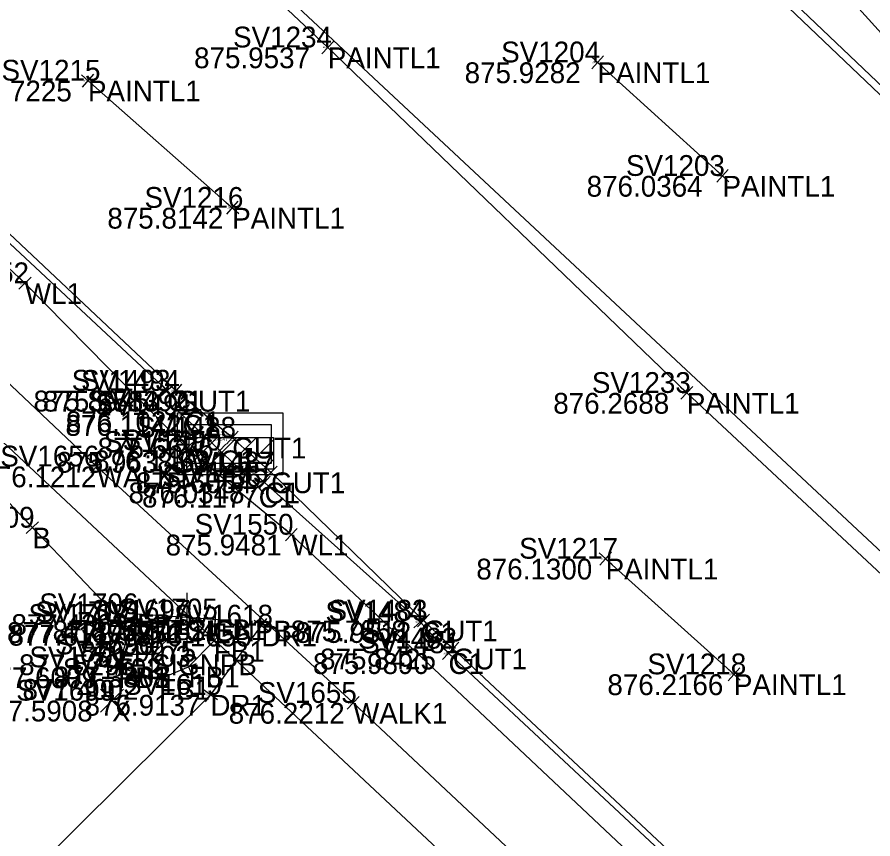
# Model space of a CAD drawing. Extents: x 1469677 to 1493262, y 375219 to 389293.
# Drawn here: x 1480224.64 to 1480274.04, y 379313.52 to 379360.96 of the extents above; entities that cross this region are included whole.
import ezdxf

# ---------------------------------------------------------------- set-up
doc = ezdxf.new("R2010")
doc.units = 0
for name, color, linetype in [('Building', 7, 'Continuous'), ('Default', 7, 'Continuous'), ('DR_X_Drive_Pipe', 7, 'Continuous'), ('DV_X_Lot_Line', 7, 'Continuous'), ('DV_X_Text', 7, 'Continuous'), ('GK_Visualization', 7, 'Continuous'), ('PNTELEV', 7, 'Continuous'), ('RD_P_Text', 7, 'Continuous'), ('RW_P_Esmt_SW', 7, 'Continuous'), ('RW_P_Esmt_U', 7, 'Continuous'), ('RW_X_CL_20', 7, 'Continuous'), ('rw_x_right_of_way', 7, 'Continuous'), ('SV_X_Mon_Cells_Found', 7, 'Continuous'), ('SV_X_Random_Point', 7, 'Continuous'), ('SV_X_Text_Elevation', 7, 'Continuous'), ('text', 7, 'Continuous'), ('Text Border', 7, 'Continuous'), ('Text Property', 7, 'Continuous')]:
    doc.layers.add(name, color=color, linetype=linetype)

msp = doc.modelspace()

# ---------------------------------------------------------------- linework, layer by layer
at = {"layer": 'Building'}
for points in [[(1480349.171, 379259.048), (1480326.954, 379280.06), (1480305.568, 379299.916), (1480284.393, 379319.578), (1480263.301, 379339.268), (1480242.575, 379359.213), (1480224.612, 379376.165), (1480208.191, 379391.527)], [(1480265.361, 379351.797), (1480258.147, 379358.351)], [(1480228.73, 379357.297), (1480237.057, 379349.954)], [(1480258.612, 379329.697), (1480266.018, 379323.022)]]:
    msp.add_lwpolyline(points, dxfattribs=at)
at = {"layer": 'Default'}
msp.add_lwpolyline([(1480232.416, 379324.173), (1480234.446, 379326.119)], dxfattribs=at)
at = {"layer": 'DR_X_Drive_Pipe'}
for points in [[(1480172.622, 379452.503), (1480197.813, 379429.111), (1480212.628, 379415.684), (1480231.592, 379398.237), (1480249.493, 379381.828), (1480253.44, 379378.963), (1480259.284, 379374.539), (1480264.171, 379372.865), (1480269.434, 379369.248), (1480270.598, 379368.157), (1480270.755, 379365.904), (1480271.186, 379363.733), (1480285.468, 379347.959), (1480298.848, 379335.614), (1480313.013, 379322.705), (1480330.745, 379305.601), (1480344.344, 379292.312), (1480351.783, 379285.136)], [(1480327.263, 379249.797), (1480312.798, 379263.799), (1480291.915, 379283.182), (1480274.385, 379298.987), (1480265.401, 379307.725), (1480264.495, 379308.458), (1480240.472, 379331.084), (1480234.677, 379335.863), (1480225.088, 379345.601), (1480208.322, 379361.342), (1480207.346, 379362.25), (1480199.528, 379369.768), (1480193.21, 379375.651), (1480182.823, 379385.139), (1480177.927, 379389.525), (1480169.423, 379398.321), (1480161.035, 379406.189), (1480144.924, 379421.019), (1480134.739, 379430.559), (1480121.485, 379441.998)]]:
    msp.add_lwpolyline(points, dxfattribs=at)
at = {"layer": 'DV_X_Lot_Line'}
msp.add_lwpolyline([(1480327.959, 379242.083), (1480313.163, 379256.356), (1480297.576, 379270.674), (1480283.951, 379284.205), (1480267.344, 379299.69), (1480258.509, 379307.782), (1480244.036, 379321.372), (1480229.243, 379335.021), (1480213.414, 379349.982), (1480196.806, 379366.202), (1480192.296, 379370.271), (1480186.385, 379375.802), (1480181.8, 379379.27), (1480179.258, 379381.212), (1480177.445, 379382.131), (1480174.921, 379382.868), (1480171.98, 379383.537), (1480169.491, 379383.403), (1480167.014, 379382.902), (1480162.891, 379380.83), (1480161.298, 379379.691), (1480158.915, 379377.808)], dxfattribs=at)
at = {"layer": 'PNTELEV'}
for p, q in [((1480242.935, 379358.866), (1480242.215, 379359.56)), ((1480242.228, 379358.853), (1480242.922, 379359.573)), ((1480242.575, 379359.213), (1480242.575, 379359.213)), ((1480258.517, 379358.014), (1480257.777, 379358.687)), ((1480257.811, 379357.98), (1480258.483, 379358.721)), ((1480258.147, 379358.351), (1480258.147, 379358.351)), ((1480228.355, 379357.628), (1480229.105, 379356.966)), ((1480229.06, 379357.672), (1480228.399, 379356.922)), ((1480228.73, 379357.297), (1480228.73, 379357.297)), ((1480265.025, 379351.427), (1480265.697, 379352.168)), ((1480265.731, 379351.461), (1480264.991, 379352.134)), ((1480265.361, 379351.797), (1480265.361, 379351.797)), ((1480236.681, 379350.285), (1480237.432, 379349.623)), ((1480237.387, 379350.329), (1480236.726, 379349.579)), ((1480237.057, 379349.954), (1480237.057, 379349.954)), ((1480224.732, 379345.251), (1480225.444, 379345.952)), ((1480225.439, 379345.245), (1480224.737, 379345.958)), ((1480225.088, 379345.601), (1480225.088, 379345.601)), ((1480232.919, 379339.073), (1480233.676, 379339.727)), ((1480233.624, 379339.022), (1480232.97, 379339.779)), ((1480233.297, 379339.4), (1480233.297, 379339.4)), ((1480234.213, 379339.069), (1480233.447, 379339.711)), ((1480233.509, 379339.006), (1480234.151, 379339.773)), ((1480233.83, 379339.39), (1480233.83, 379339.39)), ((1480263.666, 379338.927), (1480262.935, 379339.609)), ((1480262.959, 379338.903), (1480263.642, 379339.634)), ((1480263.301, 379339.268), (1480263.301, 379339.268)), ((1480234.55, 379337.645), (1480233.824, 379338.332)), ((1480233.843, 379337.626), (1480234.531, 379338.351)), ((1480233.907, 379338.477), (1480234.748, 379337.937)), ((1480234.058, 379337.787), (1480234.598, 379338.628)), ((1480234.187, 379337.989), (1480234.187, 379337.989)), ((1480234.328, 379338.207), (1480234.328, 379338.207)), ((1480237.437, 379336.35), (1480236.692, 379337.017)), ((1480236.731, 379336.311), (1480237.398, 379337.056)), ((1480237.065, 379336.683), (1480237.065, 379336.683)), ((1480235.063, 379335.545), (1480234.291, 379336.181)), ((1480234.359, 379335.477), (1480234.995, 379336.249)), ((1480234.677, 379335.863), (1480234.677, 379335.863)), ((1480236.706, 379335.606), (1480235.975, 379336.288)), ((1480235.999, 379335.582), (1480236.682, 379336.313)), ((1480236.341, 379335.947), (1480236.341, 379335.947)), ((1480229.61, 379334.682), (1480228.876, 379335.36)), ((1480228.904, 379334.654), (1480229.582, 379335.389)), ((1480229.243, 379335.021), (1480229.243, 379335.021)), ((1480239.66, 379334.332), (1480238.943, 379335.028)), ((1480238.953, 379334.321), (1480239.65, 379335.039)), ((1480239.297, 379333.763), (1480238.552, 379334.43)), ((1480238.591, 379333.724), (1480239.258, 379334.469)), ((1480239.302, 379334.68), (1480239.302, 379334.68)), ((1480238.992, 379334.145), (1480238.18, 379333.56)), ((1480238.878, 379333.447), (1480238.294, 379334.258)), ((1480238.925, 379334.096), (1480238.925, 379334.096)), ((1480238.586, 379333.852), (1480238.586, 379333.852)), ((1480225.16, 379331.144), (1480225.884, 379331.834)), ((1480225.867, 379331.128), (1480225.177, 379331.851)), ((1480225.522, 379331.489), (1480225.522, 379331.489)), ((1480240.835, 379330.741), (1480240.108, 379331.427)), ((1480240.129, 379330.72), (1480240.814, 379331.448)), ((1480240.472, 379331.084), (1480240.472, 379331.084)), ((1480258.24, 379330.032), (1480258.983, 379329.363)), ((1480258.946, 379330.069), (1480258.277, 379329.326)), ((1480258.612, 379329.697), (1480258.612, 379329.697)), ((1480231.538, 379325.994), (1480231.604, 379326.992)), ((1480232.07, 379326.46), (1480231.072, 379326.526)), ((1480231.571, 379326.493), (1480231.571, 379326.493)), ((1480236.051, 379325.696), (1480236.121, 379326.694)), ((1480248.47, 379325.78), (1480247.748, 379326.472)), ((1480247.763, 379325.765), (1480248.455, 379326.487)), ((1480230.52, 379325.533), (1480231.244, 379326.224)), ((1480231.227, 379325.517), (1480230.537, 379326.24)), ((1480231.683, 379325.757), (1480230.849, 379326.311)), ((1480231.543, 379326.451), (1480230.989, 379325.617)), ((1480231.266, 379326.034), (1480231.266, 379326.034)), ((1480235.587, 379326.23), (1480236.585, 379326.16)), ((1480236.086, 379326.195), (1480236.086, 379326.195)), ((1480239.139, 379325.541), (1480238.333, 379326.133)), ((1480239.032, 379326.24), (1480238.44, 379325.434)), ((1480247.548, 379325.701), (1480248.289, 379326.371)), ((1480248.254, 379325.665), (1480247.583, 379326.407)), ((1480247.919, 379326.036), (1480247.919, 379326.036)), ((1480248.109, 379326.126), (1480248.109, 379326.126)), ((1480230.882, 379325.878), (1480230.882, 379325.878)), ((1480238.736, 379325.837), (1480238.736, 379325.837)), ((1480235.641, 379325.295), (1480236.355, 379324.594)), ((1480235.647, 379324.588), (1480236.349, 379325.301)), ((1480235.998, 379324.944), (1480235.998, 379324.944)), ((1480249.909, 379323.899), (1480249.177, 379324.581)), ((1480249.202, 379323.874), (1480249.884, 379324.605)), ((1480250.164, 379324.164), (1480249.435, 379324.848)), ((1480249.458, 379324.141), (1480250.141, 379324.871)), ((1480249.8, 379324.506), (1480249.8, 379324.506)), ((1480249.543, 379324.24), (1480249.543, 379324.24)), ((1480229.989, 379323.563), (1480230.951, 379323.289)), ((1480230.607, 379323.907), (1480230.333, 379322.945)), ((1480234.08, 379323.269), (1480235.002, 379323.656)), ((1480234.348, 379323.924), (1480234.734, 379323.001)), ((1480230.47, 379323.426), (1480230.47, 379323.426)), ((1480232.979, 379323.231), (1480232.705, 379322.269)), ((1480234.541, 379323.463), (1480234.541, 379323.463)), ((1480265.646, 379323.357), (1480266.389, 379322.688)), ((1480266.352, 379323.394), (1480265.683, 379322.651)), ((1480266.018, 379323.022), (1480266.018, 379323.022)), ((1480232.361, 379322.887), (1480233.323, 379322.613)), ((1480232.842, 379322.75), (1480232.842, 379322.75)), ((1480236.203, 379321.541), (1480235.397, 379322.133)), ((1480236.096, 379322.24), (1480235.504, 379321.434)), ((1480235.8, 379321.837), (1480235.8, 379321.837)), ((1480244.401, 379321.029), (1480243.671, 379321.714)), ((1480243.694, 379321.007), (1480244.378, 379321.736)), ((1480244.036, 379321.372), (1480244.036, 379321.372))]:
    msp.add_line(p, q, dxfattribs=at)
at = {"layer": 'RD_P_Text'}
for points in [[(1480186.975, 379439.363), (1480207.407, 379420.301), (1480210.41, 379417.305), (1480211.712, 379416.16), (1480212.774, 379415.29), (1480213.67, 379414.243), (1480215.361, 379412.945), (1480216.632, 379411.517), (1480217.745, 379410.456), (1480218.76, 379409.536), (1480221.908, 379406.565), (1480233.156, 379396.15), (1480249.934, 379380.311), (1480262.014, 379368.886), (1480262.346, 379369.254), (1480264.513, 379367.165), (1480266.627, 379365.06), (1480266.41, 379364.736), (1480284.493, 379347.537), (1480298.919, 379333.838), (1480300.736, 379332.585), (1480315.855, 379318.308), (1480323.784, 379310.749)], [(1480186.493, 379438.955), (1480206.919, 379419.855), (1480210.187, 379416.932), (1480211.433, 379415.804), (1480213.11, 379414.171), (1480218.471, 379409.217), (1480217.005, 379410.473), (1480215.222, 379412.175), (1480221.495, 379406.235), (1480232.955, 379395.538), (1480249.633, 379380.044), (1480261.648, 379368.645), (1480263.97, 379366.423), (1480266.337, 379364.241), (1480284.168, 379347.237), (1480298.679, 379333.414), (1480300.396, 379332.229), (1480315.326, 379318.045), (1480323.87, 379309.98), (1480343.087, 379291.663), (1480360.248, 379275.585)], [(1480264.304, 379310.926), (1480249.8, 379324.506), (1480248.109, 379326.126), (1480239.302, 379334.68), (1480237.065, 379336.683), (1480233.83, 379339.39), (1480215.875, 379356.288), (1480200.731, 379370.664), (1480190.903, 379379.712), (1480187.53, 379382.642), (1480185.615, 379384.173), (1480181.928, 379385.583), (1480179.411, 379386.173), (1480174.793, 379387.235), (1480172.715, 379387.432), (1480170.332, 379387.359), (1480168.876, 379387.382), (1480166.808, 379386.944), (1480164.881, 379386.368), (1480162.883, 379385.531), (1480159.898, 379383.853), (1480158.052, 379382.754), (1480156.183, 379381.403), (1480155.05, 379380.342)], [(1480264.058, 379310.698), (1480249.543, 379324.24), (1480247.919, 379326.036), (1480238.925, 379334.096), (1480238.586, 379333.852), (1480236.341, 379335.947), (1480234.187, 379337.989), (1480234.328, 379338.207), (1480233.297, 379339.4), (1480215.447, 379356.074)]]:
    msp.add_lwpolyline(points, dxfattribs=at)
at = {"layer": 'RW_P_Esmt_U'}
for p, q in [((1480229.449, 379320.836), (1480230.783, 379322.171)), ((1480229.449, 379322.171), (1480230.783, 379320.836))]:
    msp.add_line(p, q, dxfattribs=at)
at = {"layer": 'RW_X_CL_20'}
for p, q in [((1480236.94, 379338.114), (1480236.94, 379338.114)), ((1480236.94, 379337.447), (1480236.94, 379337.447)), ((1480236.94, 379336.697), (1480236.94, 379336.697)), ((1480236.94, 379336.697), (1480236.94, 379336.697)), ((1480234.565, 379336.322), (1480234.565, 379336.322)), ((1480236.94, 379336.322), (1480236.94, 379336.322)), ((1480239.315, 379336.322), (1480239.315, 379336.322)), ((1480236.94, 379335.197), (1480236.94, 379335.197)), ((1480236.94, 379334.531), (1480236.94, 379334.531))]:
    msp.add_line(p, q, dxfattribs=at)
at = {"layer": 'rw_x_right_of_way'}
for p, q in [((1480234.446, 379327.719), (1480234.446, 379324.519)), ((1480234.446, 379326.119), (1480232.846, 379326.119)), ((1480232.416, 379325.773), (1480232.416, 379322.573)), ((1480232.416, 379324.173), (1480230.816, 379324.173))]:
    msp.add_line(p, q, dxfattribs=at)
at = {"layer": 'SV_X_Mon_Cells_Found'}
msp.add_lwpolyline([(1477164.629, 382297.849), (1479615.888, 379904.59), (1480413.414, 379159.216)], dxfattribs=at)
at = {"layer": 'SV_X_Random_Point'}
for p, q in [((1480234.44, 379334.939), (1480236.194, 379336.697)), ((1480234.44, 379336.071), (1480235.064, 379336.697)), ((1480235.496, 379334.864), (1480237.324, 379336.697)), ((1480236.625, 379334.864), (1480238.454, 379336.697)), ((1480237.755, 379334.864), (1480239.44, 379336.553)), ((1480238.885, 379334.864), (1480239.44, 379335.42))]:
    msp.add_line(p, q, dxfattribs=at)
for points in [[(1480233.898, 379338.115), (1480239.982, 379338.115), (1480239.982, 379334.531), (1480233.898, 379334.531)], [(1480234.565, 379337.447), (1480239.315, 379337.447), (1480239.315, 379335.197), (1480234.565, 379335.197)], [(1480234.44, 379336.697), (1480239.44, 379336.697), (1480239.44, 379334.864), (1480234.44, 379334.864)]]:
    msp.add_lwpolyline(points, close=True, dxfattribs=at)
at = {"layer": 'SV_X_Text_Elevation'}
msp.add_line((1479636.611, 379926.284), (1480557.828, 379065.308), dxfattribs=at)
at = {"layer": 'text'}
msp.add_lwpolyline([(1480230.882, 379325.878), (1480225.522, 379331.489), (1480218.264, 379339.152), (1480211.865, 379343.732), (1480205.22, 379349.624), (1480204.187, 379352.051), (1480200.993, 379355.729), (1480195.628, 379356.44), (1480192.91, 379360.091)], dxfattribs=at)
at = {"layer": 'Text Border'}
msp.add_lwpolyline([(1480238.736, 379325.837), (1480235.8, 379321.837), (1480220.406, 379306.568)], dxfattribs=at)
at = {"layer": 'Text Property'}
msp.add_lwpolyline([(1480230.47, 379323.426), (1480232.842, 379322.75), (1480234.541, 379323.463), (1480235.998, 379324.944), (1480236.086, 379326.195), (1480231.571, 379326.493), (1480231.266, 379326.034)], close=True, dxfattribs=at)

# ---------------------------------------------------------------- texts
at = {"layer": 'DV_X_Text'}
for s, height, p in [('875.9537', 1.2, (1480234.856, 379358.013)), ('875.95', 0.06, (1480242.294, 379359.153)), ('875.9282', 1.2, (1480250.475, 379357.151)), ('875.93', 0.06, (1480257.866, 379358.291)), ('875.7225', 1.2, (1480221.105, 379356.097)), ('875.72', 0.06, (1480228.451, 379357.237)), ('876.0364', 1.2, (1480257.519, 379350.597)), ('876.04', 0.06, (1480265.075, 379351.737)), ('875.8142', 1.2, (1480229.848, 379348.754)), ('875.81', 0.06, (1480236.799, 379349.894)), ('875.85', 0.06, (1480224.808, 379345.541)), ('875.8945', 1.2, (1480225.588, 379338.2)), ('875.6583', 1.2, (1480226.13, 379338.19)), ('875.89', 0.06, (1480233.016, 379339.34)), ('875.66', 0.06, (1480233.545, 379339.33)), ('876.2688', 1.2, (1480255.591, 379338.068)), ('876.27', 0.06, (1480263.021, 379339.208)), ('876.1142', 1.2, (1480227.433, 379336.789)), ('876.1021', 1.2, (1480227.457, 379337.007)), ('876.11', 0.06, (1480233.952, 379337.929)), ('876.10', 0.06, (1480234.065, 379338.147)), ('875.6676', 1.2, (1480229.289, 379335.483)), ('875.6547', 0.2, (1480235.655, 379336.497)), ('875.67', 0.06, (1480236.784, 379336.623)), ('875.65', 0.01, (1480236.893, 379336.687)), ('875.9638', 1.2, (1480226.929, 379334.663)), ('876.1463', 1.2, (1480229.085, 379334.747)), ('875.96', 0.06, (1480234.392, 379335.803)), ('876.15', 0.06, (1480236.084, 379335.887)), ('876.1212', 1.2, (1480222.517, 379333.821)), ('876.12', 0.06, (1480228.986, 379334.961)), ('875.6054', 1.2, (1480231.497, 379333.48)), ('875.61', 0.06, (1480239.043, 379334.62)), ('876.0348', 1.2, (1480231.073, 379332.896)), ('876.1177', 1.2, (1480231.85, 379332.652)), ('876.03', 0.06, (1480238.638, 379334.036)), ('876.12', 0.06, (1480238.329, 379333.792)), ('877.39', 0.06, (1480225.241, 379331.429)), ('875.9481', 1.2, (1480233.213, 379329.884)), ('875.95', 0.06, (1480240.191, 379331.024)), ('876.1300', 1.2, (1480251.148, 379328.497)), ('876.13', 0.06, (1480258.355, 379329.637)), ('877.4361', 1.2, (1480224.313, 379325.293)), ('877.44', 0.06, (1480231.292, 379326.433)), ('877.4189', 1.2, (1480224.058, 379324.834)), ('877.0577', 1.2, (1480226.689, 379324.919)), ('876.8182', 1.2, (1480228.868, 379324.995)), ('877.42', 0.06, (1480230.987, 379325.974)), ('877.06', 0.06, (1480234.157, 379326.059)), ('876.82', 0.06, (1480235.805, 379326.135)), ('875.7858', 1.2, (1480240.437, 379324.926)), ('875.9512', 1.2, (1480240.701, 379324.836)), ('875.95', 0.06, (1480247.638, 379325.976)), ('875.79', 0.06, (1480247.829, 379326.066)), ('877.6117', 1.2, (1480224.147, 379324.678)), ('877.61', 0.06, (1480230.624, 379325.818)), ('876.1655', 1.2, (1480231.49, 379324.637)), ('876.17', 0.06, (1480238.479, 379325.777)), ('876.9975', 1.2, (1480228.279, 379323.744)), ('877.00', 0.06, (1480235.708, 379324.884)), ('875.8425', 1.2, (1480242.128, 379323.306)), ('875.84', 0.06, (1480249.52, 379324.446)), ('877.5295', 1.2, (1480224.754, 379322.973)), ('877.53', 0.06, (1480232.137, 379324.113)), ('875.9890', 1.2, (1480241.72, 379323.04)), ('875.99', 0.06, (1480249.261, 379324.18)), ('877.6009', 1.2, (1480222.552, 379322.226)), ('877.3803', 1.2, (1480226.746, 379322.263)), ('877.60', 0.06, (1480230.185, 379323.366)), ('877.38', 0.06, (1480234.26, 379323.403)), ('876.2166', 1.2, (1480258.715, 379321.822)), ('876.22', 0.06, (1480265.738, 379322.962)), ('877.4002', 1.2, (1480224.953, 379321.55)), ('877.40', 0.06, (1480232.557, 379322.69)), ('877.5908', 1.2, (1480222.312, 379320.303)), ('876.9137', 1.2, (1480228.535, 379320.637)), ('876.91', 0.06, (1480235.541, 379321.777)), ('877.59', 0.06, (1480229.836, 379321.443)), ('876.2212', 1.2, (1480236.856, 379320.172)), ('876.22', 0.06, (1480243.756, 379321.312))]:
    msp.add_text(s, height=height, dxfattribs=at).set_placement(p)
at = {"layer": 'GK_Visualization'}
for s, height, p in [('PAINTL1', 1.2, (1480242.575, 379358.013)), ('PAINTL1', 1.2, (1480258.147, 379357.151)), ('PAINTL1', 1.2, (1480228.73, 379356.097)), ('PAINTL1', 1.2, (1480265.361, 379350.597)), ('PAINTL1', 1.2, (1480237.057, 379348.754)), ('WL1', 1.2, (1480225.088, 379344.401)), ('C1', 1.2, (1480233.297, 379338.2)), ('GUT1', 1.2, (1480233.83, 379338.19)), ('PAINTL1', 1.2, (1480263.301, 379338.068)), ('C1', 1.2, (1480234.187, 379336.789)), ('C1', 1.2, (1480234.328, 379337.007)), ('CB-3', 0.2, (1480236.94, 379336.497)), ('GUT1', 1.2, (1480237.065, 379335.483)), ('WL1', 1.2, (1480234.677, 379334.663)), ('C1', 1.2, (1480236.341, 379334.747)), ('WALK1', 1.2, (1480229.243, 379333.821)), ('GUT1', 1.2, (1480239.302, 379333.48)), ('C1', 1.2, (1480238.586, 379332.652)), ('C1', 1.2, (1480238.925, 379332.896)), ('B', 1.2, (1480225.522, 379330.289)), ('WL1', 1.2, (1480240.472, 379329.884)), ('PAINTL1', 1.2, (1480258.612, 379328.497)), ('FB1', 1.2, (1480231.571, 379325.293)), ('FB1', 1.2, (1480231.266, 379324.834)), ('SIGNPB', 1.2, (1480234.446, 379324.919)), ('FB1', 1.2, (1480236.086, 379324.995)), ('C1', 1.2, (1480247.919, 379324.836)), ('GUT1', 1.2, (1480248.109, 379324.926)), ('B', 1.2, (1480230.882, 379324.678)), ('DR1', 1.2, (1480238.736, 379324.637)), ('FB1', 1.2, (1480235.998, 379323.744)), ('GUT1', 1.2, (1480249.8, 379323.306)), ('SIGNPB', 1.2, (1480232.416, 379322.973)), ('C1', 1.2, (1480249.543, 379323.04)), ('FB1', 1.2, (1480230.47, 379322.226)), ('FB1', 1.2, (1480234.541, 379322.263)), ('PAINTL1', 1.2, (1480266.018, 379321.822)), ('FB1', 1.2, (1480232.842, 379321.55)), ('DR1', 1.2, (1480235.8, 379320.637)), ('X', 1.2, (1480230.116, 379320.303)), ('WALK1', 1.2, (1480244.036, 379320.172))]:
    msp.add_text(s, height=height, dxfattribs=at).set_placement(p)
at = {"layer": 'RW_P_Esmt_SW'}
for s, height, p in [('SV1234', 1.2, (1480237.105, 379359.213)), ('SV1204', 1.2, (1480252.583, 379358.351)), ('SV1234', 0.06, (1480242.302, 379359.213)), ('SV1215', 1.2, (1480223.742, 379357.297)), ('SV1204', 0.06, (1480257.869, 379358.351)), ('SV1215', 0.06, (1480228.481, 379357.297)), ('SV1203', 1.2, (1480259.787, 379351.797)), ('SV1203', 0.06, (1480265.082, 379351.797)), ('SV1216', 1.2, (1480231.994, 379349.954)), ('SV1216', 0.06, (1480236.804, 379349.954)), ('SV1552', 1.2, (1480219.618, 379345.601)), ('SV1552', 0.06, (1480224.815, 379345.601)), ('SV1493', 1.2, (1480227.79, 379339.4)), ('SV1494', 1.2, (1480228.332, 379339.39)), ('SV1233', 1.2, (1480257.821, 379339.268)), ('SV1492', 1.2, (1480228.829, 379338.207)), ('SV1493', 0.06, (1480233.022, 379339.4)), ('SV1494', 0.06, (1480233.555, 379339.39)), ('SV1233', 0.06, (1480263.027, 379339.268)), ('SV1491', 1.2, (1480229.131, 379337.989)), ('SV1488', 1.2, (1480231.567, 379336.683)), ('SV1491', 0.06, (1480233.934, 379337.989)), ('SV1492', 0.06, (1480234.053, 379338.207)), ('SV1551', 1.2, (1480229.649, 379335.863)), ('SV1490', 1.2, (1480230.729, 379335.947)), ('SV1489', 0.2, (1480236.024, 379336.697)), ('SV1488', 0.06, (1480236.79, 379336.683)), ('SV1489', 0.01, (1480236.894, 379336.697)), ('SV1656', 1.2, (1480223.669, 379335.021)), ('SV1487', 1.2, (1480233.813, 379334.68)), ('SV1551', 0.06, (1480234.426, 379335.863)), ('SV1490', 0.06, (1480236.06, 379335.947)), ('SV1656', 0.06, (1480228.964, 379335.021)), ('SV1486', 1.2, (1480233.022, 379333.852)), ('SV1485', 1.2, (1480233.436, 379334.096)), ('SV1487', 0.06, (1480239.028, 379334.68)), ('SV1486', 0.06, (1480238.308, 379333.852)), ('SV1485', 0.06, (1480238.651, 379334.096)), ('SV1709', 1.2, (1480219.939, 379331.489)), ('SV1550', 1.2, (1480234.888, 379331.084)), ('SV1709', 0.06, (1480225.243, 379331.489)), ('SV1550', 0.06, (1480240.193, 379331.084)), ('SV1217', 1.2, (1480253.624, 379329.697)), ('SV1217', 0.06, (1480258.363, 379329.697)), ('SV1706', 1.2, (1480225.922, 379326.493)), ('SV1708', 1.2, (1480225.299, 379325.878)), ('SV1707', 1.2, (1480225.692, 379326.034)), ('SV1697', 1.2, (1480228.929, 379326.119)), ('SV1705', 1.2, (1480230.512, 379326.195)), ('SV1618', 1.2, (1480233.701, 379325.837)), ('SV1484', 1.2, (1480242.439, 379326.036)), ('SV1483', 1.2, (1480242.62, 379326.126)), ('SV1706', 0.06, (1480231.289, 379326.493)), ('SV1704', 1.2, (1480230.434, 379324.944)), ('SV1707', 0.06, (1480230.987, 379326.034)), ('SV1697', 0.06, (1480234.17, 379326.119)), ('SV1705', 0.06, (1480235.807, 379326.195)), ('SV1484', 0.06, (1480247.645, 379326.036)), ('SV1483', 0.06, (1480247.835, 379326.126)), ('SV1708', 0.06, (1480230.603, 379325.878)), ('SV1618', 0.06, (1480238.484, 379325.837)), ('SV1482', 1.2, (1480244.32, 379324.506)), ('SV1696', 1.2, (1480226.823, 379324.173)), ('SV1704', 0.06, (1480235.72, 379324.944)), ('SV1481', 1.2, (1480244.506, 379324.24)), ('SV1701', 1.2, (1480225.347, 379323.426)), ('SV1703', 1.2, (1480228.967, 379323.463)), ('SV1482', 0.06, (1480249.526, 379324.506)), ('SV1696', 0.06, (1480232.136, 379324.173)), ('SV1481', 0.06, (1480249.291, 379324.24)), ('SV1218', 1.2, (1480261.021, 379323.022)), ('SV1702', 1.2, (1480227.278, 379322.75)), ('SV1703', 0.06, (1480234.262, 379323.463)), ('SV1701', 0.06, (1480230.214, 379323.426)), ('SV1619', 1.2, (1480230.765, 379321.837)), ('SV1218', 0.06, (1480265.768, 379323.022)), ('SV1699', 1.2, (1480224.589, 379321.503)), ('SV1702', 0.06, (1480232.564, 379322.75)), ('SV1655', 1.2, (1480238.538, 379321.372)), ('SV1699', 0.06, (1480229.84, 379321.503)), ('SV1619', 0.06, (1480235.548, 379321.837)), ('SV1655', 0.06, (1480243.761, 379321.372))]:
    msp.add_text(s, height=height, dxfattribs=at).set_placement(p)

doc.saveas('drawing.dxf')
